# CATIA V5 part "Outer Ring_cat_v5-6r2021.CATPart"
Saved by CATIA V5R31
Part number: Outer Ring
Bounding box of the stored display mesh (mm): x -99.819 to 99.819, y 0 to 50, z -100 to 100
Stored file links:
  D:\PROJECTS\Project 2021\US EDITION\CATIA V5 6R 2021\Resources\Tutorial Files\c16_catia_v5_6r2021_tut\Bearing\Outer Ring_cat_v5-6r2021.CATPart
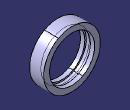
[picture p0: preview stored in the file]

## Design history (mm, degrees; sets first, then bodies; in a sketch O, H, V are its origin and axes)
Body1 (main body)
  Sketch1 on yz-plane, origin (0, 0, 0), H (0, 1, 0), V (0, 0, 1)
    point P1 (0, 80)
    line L1 (0, 80) -> (0, 100)
    line L2 (0, 100) -> (50, 100)
    line L3 (50, 100) -> (50, 80)
    line L4 (50, 80) -> (35, 80)
    line L5 (35, 80) -> (35, 85)
    line L6 (35, 85) -> (15, 85)
    line L7 (15, 85) -> (15, 80)
    point P8 (15, 80)
    line L8 (15, 80) -> (0, 80)
    point P9 (0, 80)
    distance H L8 = 80
    length L2 = 50
    length L5 = 5
    length L8 = 15
    length L4 = 15
    length L1 = 20
    coincidence: P1 V, P8 L4, P9 V, P9 P1
    vertical: L1 V, L3 V, L5 V, L7 V
    horizontal: L2 H, L4 H, L6 H, L8 H
  Shaft1: profile Sketch1, axis Sketch1.H, angle 360
  Plane1: type Offset, RefPlane face of Shaft1 from Sketch1.L5, Offset 10, reversed
  Sketch2 on Plane1, origin (0, 25, 0), H (-1, 0, 0), V (0, 0, 1)
    projected circle E1 centre (0, 0) radius 85 from edge [face of Shaft1 from Sketch1.L6 | face of Shaft1 from Sketch1.L7]
  Point1: type OnCurve, Support Sketch2, RefPoint {extremum Reference Sketch2, Direction (1, 2, 3)}, Length 282.187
